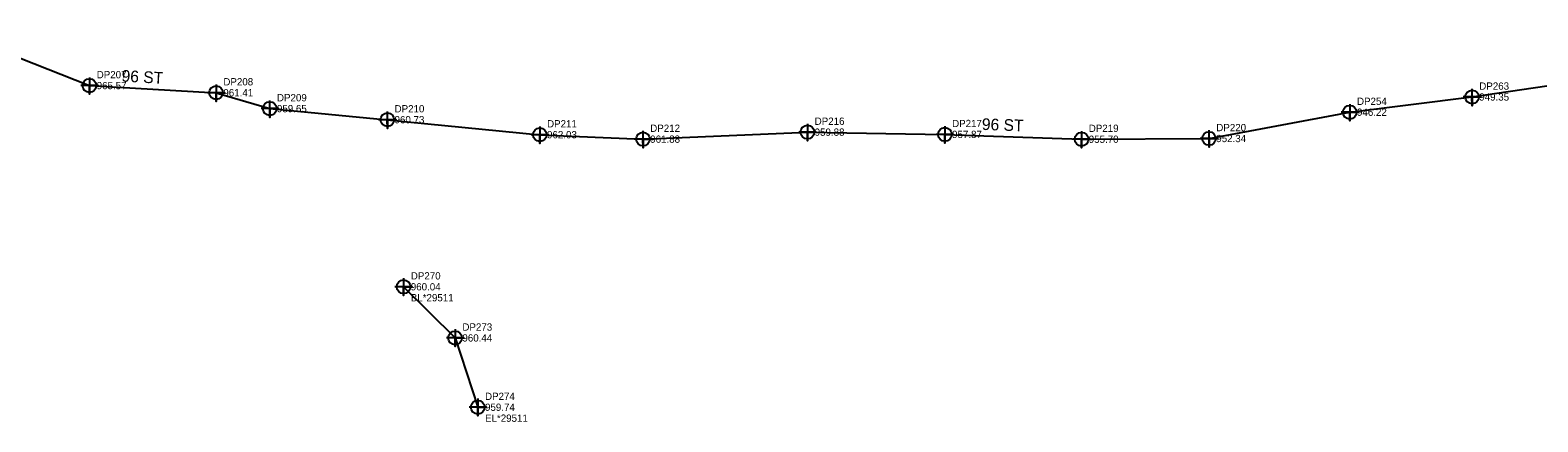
# Model space of a CAD drawing. Extents: x 1182504 to 1186036, y 573002 to 575111.
# Drawn here: x 1184495 to 1185012, y 573620 to 573755 of the extents above; entities that cross this region are included whole.
import ezdxf

# ---------------------------------------------------------------- set-up
doc = ezdxf.new("R2010")
doc.units = 0
for name, color, linetype in [('Exist Utilities Power UG Cable SUE LOS B', 7, 'Continuous'), ('Exist Utilities Power UG Cable SUE LOS B Cogo Comment', 7, 'Continuous'), ('Exist Utilities Power UG Cable SUE LOS B Cogo Elevation', 7, 'Continuous'), ('Exist Utilities Power UG Cable SUE LOS B Cogo Number', 7, 'Continuous'), ('Exist Utilities Power UG Cable SUE LOS B Cogo Point CELL', 7, 'Continuous'), ('Exist Utilities Telephone UG Conduit SUE LOS B', 7, 'Continuous'), ('Exist Utilities Telephone UG Conduit SUE LOS B Cogo Elevation', 7, 'Continuous'), ('Exist Utilities Telephone UG Conduit SUE LOS B Cogo Number', 7, 'Continuous'), ('Exist Utilities Telephone UG Conduit SUE LOS B Cogo Point CELL', 7, 'Continuous'), ('Exist Utilities Telephone UG Conduit SUE LOS B Text', 7, 'Continuous')]:
    doc.layers.add(name, color=color, linetype=linetype)

msp = doc.modelspace()

# ---------------------------------------------------------------- linework, layer by layer
at = {"layer": 'Exist Utilities Power UG Cable SUE LOS B'}
msp.add_lwpolyline([(1184623.07, 573666.81), (1184640.77, 573649.24), (1184648.53, 573625.44)], dxfattribs=at)
at = {"layer": 'Exist Utilities Power UG Cable SUE LOS B Cogo Point CELL'}
for points in [[(1184623.07, 573669.81), (1184623.07, 573663.81), (1184623.07, 573666.81), (1184626.07, 573666.81), (1184620.07, 573666.81)], [(1184640.77, 573652.24), (1184640.77, 573646.24), (1184640.77, 573649.24), (1184643.77, 573649.24), (1184637.77, 573649.24)], [(1184648.53, 573628.44), (1184648.53, 573622.44), (1184648.53, 573625.44), (1184651.53, 573625.44), (1184645.53, 573625.44)]]:
    msp.add_lwpolyline(points, dxfattribs=at)
for centre in [(1184623.07, 573666.81), (1184640.77, 573649.24), (1184648.53, 573625.44)]:
    msp.add_circle(centre, 2.34, dxfattribs=at)
at = {"layer": 'Exist Utilities Telephone UG Conduit SUE LOS B'}
msp.add_lwpolyline([(1184467.17, 573754.95), (1184515.32, 573735.91), (1184558.77, 573733.46), (1184577.16, 573728), (1184617.5, 573724.19), (1184669.81, 573719.04), (1184705.2, 573717.51), (1184761.61, 573719.92), (1184808.75, 573719.14), (1184855.63, 573717.48), (1184899.38, 573717.73), (1184947.65, 573726.76), (1184989.59, 573731.99), (1185049.6, 573740.86), (1185104.23, 573742.11), (1185147.54, 573741.49), (1185190.99, 573738.17), (1185243.67, 573733.83), (1185296.19, 573730.81), (1185343.76, 573727.54), (1185391.61, 573722.1), (1185423.08, 573716.53), (1185467.66, 573711.88), (1185536.39, 573704.97)], dxfattribs=at)
at = {"layer": 'Exist Utilities Telephone UG Conduit SUE LOS B Cogo Point CELL'}
for points in [[(1184515.31, 573738.73), (1184515.34, 573732.91), (1184515.32, 573735.91), (1184518.34, 573735.91), (1184512.34, 573735.91)], [(1184558.75, 573736.28), (1184558.78, 573730.46), (1184558.77, 573733.46), (1184561.78, 573733.46), (1184555.78, 573733.46)], [(1184989.57, 573734.81), (1184989.61, 573728.99), (1184989.59, 573731.99), (1184992.61, 573731.99), (1184986.61, 573731.99)], [(1184577.15, 573730.81), (1184577.18, 573725), (1184577.16, 573728), (1184580.18, 573728), (1184574.18, 573728)], [(1184617.49, 573727.01), (1184617.52, 573721.19), (1184617.5, 573724.19), (1184620.52, 573724.19), (1184614.52, 573724.19)], [(1184947.64, 573729.57), (1184947.67, 573723.76), (1184947.65, 573726.76), (1184950.67, 573726.76), (1184944.67, 573726.76)], [(1184669.8, 573721.85), (1184669.83, 573716.04), (1184669.81, 573719.04), (1184672.83, 573719.04), (1184666.83, 573719.04)], [(1184705.19, 573720.32), (1184705.22, 573714.51), (1184705.2, 573717.51), (1184708.22, 573717.51), (1184702.22, 573717.51)], [(1184761.59, 573722.73), (1184761.63, 573716.92), (1184761.61, 573719.92), (1184764.63, 573719.92), (1184758.63, 573719.92)], [(1184808.74, 573721.96), (1184808.77, 573716.14), (1184808.75, 573719.14), (1184811.77, 573719.14), (1184805.77, 573719.14)], [(1184855.62, 573720.29), (1184855.65, 573714.48), (1184855.63, 573717.48), (1184858.65, 573717.48), (1184852.65, 573717.48)], [(1184899.36, 573720.54), (1184899.39, 573714.73), (1184899.38, 573717.73), (1184902.39, 573717.73), (1184896.39, 573717.73)]]:
    msp.add_lwpolyline(points, dxfattribs=at)
for centre in [(1184515.34, 573735.91), (1184558.78, 573733.46), (1184577.18, 573728), (1184989.61, 573731.99), (1184617.52, 573724.19), (1184947.67, 573726.76), (1184669.83, 573719.04), (1184705.22, 573717.51), (1184761.63, 573719.92), (1184808.77, 573719.14), (1184855.65, 573717.48), (1184899.39, 573717.73)]:
    msp.add_circle(centre, 2.34, dxfattribs=at)

# ---------------------------------------------------------------- texts
at = {"layer": 'Exist Utilities Power UG Cable SUE LOS B Cogo Comment'}
for s, p in [('BL*29511', (1184625.57, 573661.81)), ('EL*29511', (1184651.03, 573620.44))]:
    msp.add_text(s, height=2.5, dxfattribs=at).set_placement(p)
at = {"layer": 'Exist Utilities Power UG Cable SUE LOS B Cogo Elevation'}
for s, p in [('960.04', (1184625.57, 573665.56)), ('960.44', (1184643.27, 573647.99)), ('959.74', (1184651.03, 573624.19))]:
    msp.add_text(s, height=2.5, dxfattribs=at).set_placement(p)
at = {"layer": 'Exist Utilities Power UG Cable SUE LOS B Cogo Number'}
for s, p in [('DP270', (1184625.57, 573669.31)), ('DP273', (1184643.27, 573651.74)), ('DP274', (1184651.03, 573627.94))]:
    msp.add_text(s, height=2.5, dxfattribs=at).set_placement(p)
at = {"layer": 'Exist Utilities Telephone UG Conduit SUE LOS B Cogo Elevation'}
for s, p in [('965.57', (1184517.82, 573734.66)), ('961.41', (1184561.27, 573732.21)), ('949.35', (1184992.09, 573730.74)), ('959.65', (1184579.66, 573726.75)), ('960.73', (1184620, 573722.94)), ('946.22', (1184950.15, 573725.51)), ('962.03', (1184672.31, 573717.79)), ('959.88', (1184764.11, 573718.67)), ('957.87', (1184811.25, 573717.89)), ('961.88', (1184707.7, 573716.26)), ('955.70', (1184858.13, 573716.23)), ('952.34', (1184901.88, 573716.48))]:
    msp.add_text(s, height=2.5, dxfattribs=at).set_placement(p)
at = {"layer": 'Exist Utilities Telephone UG Conduit SUE LOS B Cogo Number'}
for s, p in [('DP207', (1184517.82, 573738.41)), ('DP208', (1184561.27, 573735.96)), ('DP263', (1184992.09, 573734.49)), ('DP209', (1184579.66, 573730.5)), ('DP254', (1184950.15, 573729.26)), ('DP210', (1184620, 573726.69)), ('DP216', (1184764.11, 573722.42)), ('DP211', (1184672.31, 573721.54)), ('DP212', (1184707.7, 573720.01)), ('DP217', (1184811.25, 573721.64)), ('DP219', (1184858.13, 573719.98)), ('DP220', (1184901.88, 573720.23))]:
    msp.add_text(s, height=2.5, dxfattribs=at).set_placement(p)
at = {"layer": 'Exist Utilities Telephone UG Conduit SUE LOS B Text'}
for rotation, p in [(356.7729, (1184526.26, 573737.3)), (357.9686, (1184821.41, 573720.69))]:
    msp.add_text('96 ST', height=4, rotation=rotation, dxfattribs=at).set_placement(p)

doc.saveas('drawing.dxf')
